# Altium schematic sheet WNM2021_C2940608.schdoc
size 127 x 101 mm
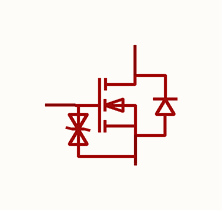
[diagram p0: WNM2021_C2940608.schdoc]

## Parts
Q?  wnm2021  [SOT-323-3_L2.2-W1.3-P1.30-LS2.1-BR]  (value not drawn)

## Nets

Not connected (* = marked no-connect by the designer): Q? 1(G) 2(S) 3(D)

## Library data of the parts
Q? = wnm2021: 漏源电压(Vdss):20V;连续漏极电流(Id):900mA;导通电阻(RDS(on)):400mΩ@4.5V;耗散功率(Pd):350mW;阈值电压(Vgs(th)):1.1V@250uA;; Manufacturer: TECH PUBLIC(台舟); Symbol: WNM2021_C2940608; AddInBom: yes; ModelId: 59529c0d6fc749f28f2d0659e12986b4; ModelName: SOT-323-3_L2.0-W1.3-H1.0-LS2.1-P1.30; ModelTransform: 78.74,82.677,0,90,0,0,-0.001,-0.001,0; Drain to Source Voltage: 20V; Current - Continuous Drain(Id): 900mA; Pd - Power Dissipation: 350mW; Input Capacitance(Ciss): 45pF; Reverse Transfer Capacitance (Crss@Vds): 6pF@10V; Output Capacitance(Coss): 6pF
